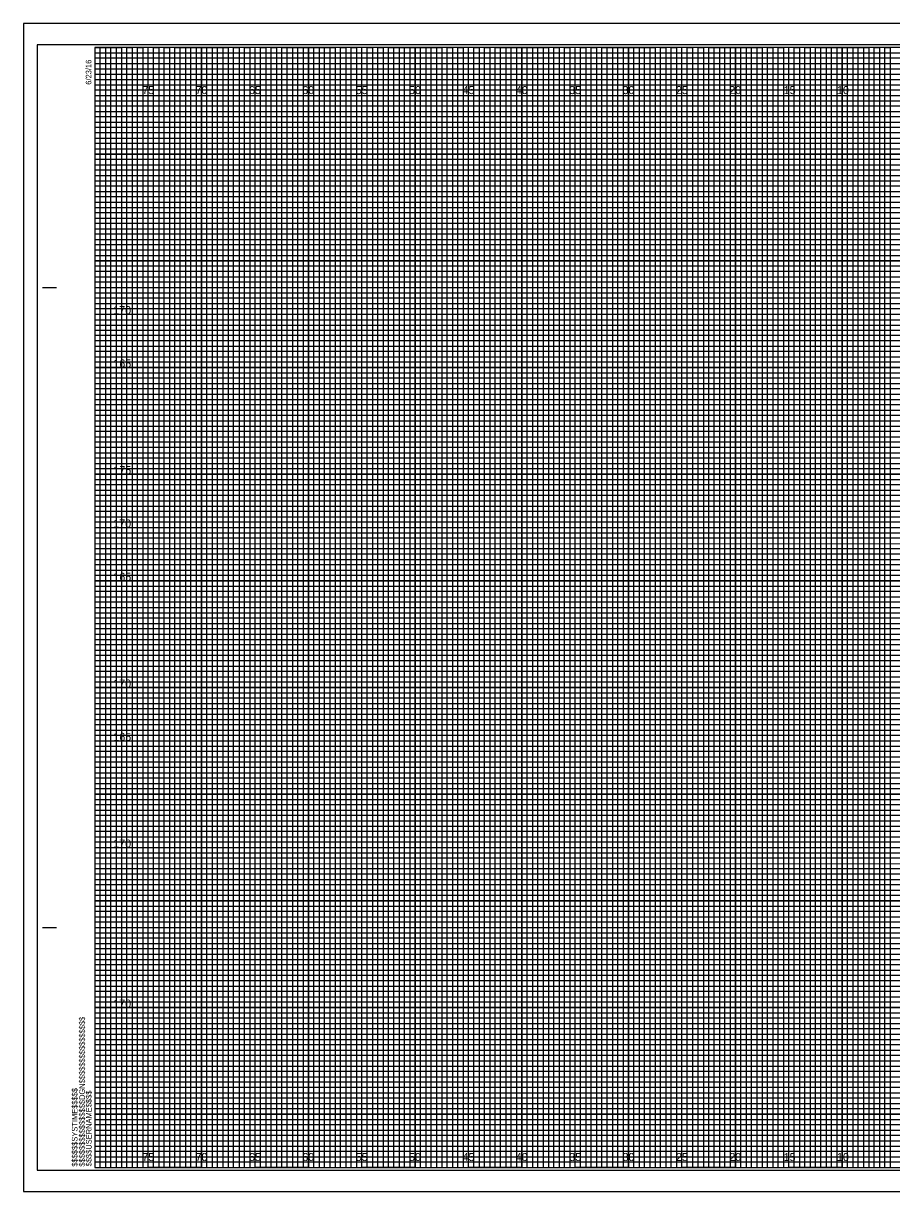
# Model space of a CAD drawing. Extents: x -7 to 162, y -2 to 107.
# Drawn here: x -6.7 to 74.6, y -2.3 to 107.3 of the extents above; entities that cross this region are included whole.
import ezdxf

# ---------------------------------------------------------------- set-up
doc = ezdxf.new("R2010")
doc.units = 0
for name, color, linetype in [('Prop XS Earthwork Shape', 7, 'Continuous'), ('Prop XS Elevation Labels', 7, 'Continuous'), ('Sheet Cross Section CELL', 7, 'Continuous'), ('Sheet Cross Section Grid Major CELL', 7, 'Continuous'), ('Sheet Cross Section Grid Middle CELL', 7, 'Continuous'), ('Sheet Cross Section Grid Minor 1 CELL', 7, 'Continuous'), ('Sheet Cross Section Grid Minor 2 CELL', 7, 'Continuous'), ('Sheet Cutting Line CELL', 7, 'Continuous'), ('Sheet DOT Grid CELL', 7, 'Continuous'), ('Sheet Plot Border Inside CELL', 7, 'Continuous'), ('Sheet Plot Border Outside CELL', 7, 'Continuous')]:
    doc.layers.add(name, color=color, linetype=linetype)

msp = doc.modelspace()

# ---------------------------------------------------------------- linework, layer by layer
at = {"layer": 'Sheet Cross Section CELL'}
for p, q in [((-4.9, 82.5), (-3.65, 82.5)), ((-4.85, 82.5), (-3.6, 82.5)), ((-4.9, 22.5), (-3.65, 22.5)), ((-4.85, 22.5), (-3.6, 22.5)), ((0, 0), (0, 0)), ((0, 0), (0, 0)), ((0, 0), (0, 0)), ((0, 0), (0, 0)), ((0, 0), (0, 0)), ((0, 0), (0, 0)), ((0, 0), (0, 0))]:
    msp.add_line(p, q, dxfattribs=at)
msp.add_lwpolyline([(160, 105), (0, 105), (0, 0), (160, 0)], close=True, dxfattribs=at)
at = {"layer": 'Sheet Cross Section Grid Major CELL'}
for p, q in [((5, 105), (0, 105)), ((5, 0), (5, 105)), ((15, 105), (10, 105)), ((10, 105), (10, 0)), ((15, 0), (15, 105)), ((25, 105), (20, 105)), ((20, 105), (20, 0)), ((25, 0), (25, 105)), ((35, 105), (30, 105)), ((30, 105), (30, 0)), ((35, 0), (35, 105)), ((45, 105), (40, 105)), ((40, 105), (40, 0)), ((45, 0), (45, 105)), ((55, 105), (50, 105)), ((50, 105), (50, 0)), ((55, 0), (55, 105)), ((65, 105), (60, 105)), ((60, 105), (60, 0)), ((65, 0), (65, 105)), ((75, 105), (70, 105)), ((70, 105), (70, 0)), ((10, 0), (5, 0)), ((20, 0), (15, 0)), ((30, 0), (25, 0)), ((40, 0), (35, 0)), ((50, 0), (45, 0)), ((60, 0), (55, 0)), ((70, 0), (65, 0))]:
    msp.add_line(p, q, dxfattribs=at)
for points in [[(0, 100), (160, 100), (160, 95), (0, 95)], [(0, 90), (160, 90), (160, 85), (0, 85)], [(0, 80), (160, 80), (160, 75), (0, 75)], [(0, 70), (160, 70), (160, 65), (0, 65)], [(0, 60), (160, 60), (160, 55), (0, 55)], [(0, 50), (160, 50), (160, 45), (0, 45)], [(0, 40), (160, 40), (160, 35), (0, 35)], [(0, 30), (160, 30), (160, 25), (0, 25)], [(0, 20), (160, 20), (160, 15), (0, 15)], [(0, 10), (160, 10), (160, 5), (0, 5)]]:
    msp.add_lwpolyline(points, dxfattribs=at)
at = {"layer": 'Sheet Cross Section Grid Middle CELL'}
for points in [[(0, 105), (2.5, 105), (2.5, 0), (7.5, 0), (7.5, 105), (12.5, 105), (12.5, 0), (17.5, 0), (17.5, 105), (22.5, 105), (22.5, 0), (27.5, 0), (27.5, 105), (32.5, 105), (32.5, 0), (37.5, 0), (37.5, 105), (42.5, 105), (42.5, 0), (47.5, 0), (47.5, 105), (52.5, 105), (52.5, 0), (57.5, 0), (57.5, 105), (62.5, 105), (62.5, 0), (67.5, 0), (67.5, 105), (72.5, 105), (72.5, 0), (77.5, 0)], [(0, 102.5), (137.5, 102.5)], [(0, 92.5), (160, 92.5), (160, 97.5), (0, 97.5)], [(0, 82.5), (160, 82.5), (160, 87.5), (0, 87.5)], [(0, 72.5), (160, 72.5), (160, 77.5), (0, 77.5)], [(0, 62.5), (160, 62.5), (160, 67.5), (0, 67.5)], [(0, 52.5), (160, 52.5), (160, 57.5), (0, 57.5)], [(0, 42.5), (160, 42.5), (160, 47.5), (0, 47.5)], [(0, 32.5), (160, 32.5), (160, 37.5), (0, 37.5)], [(0, 22.5), (160, 22.5), (160, 27.5), (0, 27.5)], [(0, 12.5), (160, 12.5), (160, 17.5), (0, 17.5)], [(0, 2.5), (160, 2.5), (160, 7.5), (0, 7.5)]]:
    msp.add_lwpolyline(points, dxfattribs=at)
at = {"layer": 'Sheet Cross Section Grid Minor 1 CELL'}
for p, q in [((0, 104.5), (130, 104.5)), ((130, 103.99), (0, 103.99)), ((0, 103.99), (0, 103.5)), ((0, 103.5), (130, 103.5)), ((130, 102.95), (0, 102.95)), ((0, 102.95), (0, 102)), ((0, 102), (160, 102))]:
    msp.add_line(p, q, dxfattribs=at)
for points in [[(0, 101.5), (135, 101.5), (160, 101.5), (160, 101), (0, 101)], [(0, 100.5), (160, 100.5), (160, 99.5), (0, 99.5)], [(0, 99), (160, 99), (160, 98.5), (0, 98.49)], [(0, 98), (160, 98), (160, 97), (0, 97)], [(0, 96.5), (160, 96.5), (160, 96), (0, 96)], [(0, 95.5), (160, 95.5), (160, 94.5), (0, 94.5)], [(0, 94), (160, 94), (160, 93.5), (0, 93.5)], [(0, 93), (160, 93), (160, 92), (0, 92)], [(0, 91.5), (160, 91.5), (160, 91), (0, 91)], [(0, 90.5), (160, 90.5), (160, 89.5), (0, 89.5)], [(0, 89), (160, 89), (160, 88.5), (0, 88.5)], [(0, 88), (160, 88), (160, 86.98), (160, 86.5), (160, 86), (0, 86)], [(0, 87), (160, 87), (160, 86.5), (0, 86.5)], [(0, 85.5), (160, 85.5), (160, 84.5), (0, 84.52)], [(0, 84.52), (160, 84.5), (160, 84), (0, 84)], [(0, 83.5), (160, 83.5), (160, 83), (0, 83)], [(0, 82), (160, 82), (160, 81.5), (0, 81.5)], [(0, 81), (160, 81), (160, 80.5), (0, 80.5)], [(-0.04, 79.45), (160, 79.45), (160, 78.94), (-0.04, 78.94)], [(0, 78.5), (160, 78.5), (160, 78), (0, 78)], [(0, 77), (160, 77), (160, 76.5), (0, 76.5)], [(0, 76), (160, 76), (160, 75.5), (0, 75.5)], [(0, 74.5), (160, 74.5), (160, 74), (0, 74)], [(0, 73.5), (160, 73.5), (160, 73), (0, 73)], [(0, 72), (160, 72), (160, 71.5), (0, 71.5)], [(0, 71), (160, 71), (160, 70.5), (0, 70.5)], [(0, 69.5), (160, 69.5), (160, 68.99), (0, 69)], [(0, 68.5), (160, 68.5), (160, 68), (0, 68)], [(0, 67), (160, 67), (160, 66.5), (0, 66.5)], [(0, 66), (160, 66), (160, 65.5), (0, 65.5)], [(0, 64.5), (160, 64.5), (160, 64), (0, 64)], [(0, 63.5), (160, 63.5), (160, 63), (0, 63)], [(0, 62), (160, 62), (160, 61.5), (0, 61.5)], [(0, 61), (160, 61), (160, 60.5), (0, 60.5)], [(0, 59.5), (160, 59.5), (160, 59), (0, 59)], [(0, 58.5), (160.03, 58.45), (160, 58), (0, 58)], [(0, 57), (160, 57), (160, 56.5), (0, 56.5)], [(0, 56), (160, 56), (160, 55.5), (0, 55.5)], [(0, 54.5), (160, 54.5), (160, 54), (0, 54)], [(0, 53.5), (160, 53.5), (160, 53), (0, 53)], [(0, 52), (160, 52), (160, 51.5), (0, 51.5)], [(0, 51), (160, 51), (160, 50.5), (0, 50.5)], [(0, 49.5), (160, 49.5), (160, 49), (0, 49)], [(0, 48.5), (160, 48.5), (160, 48), (0, 48)], [(0, 47), (160, 47), (160, 46.5), (0, 46.5)], [(0, 46), (160, 46), (160, 45.5), (0, 45.5)], [(0, 44.5), (160, 44.5), (160, 44), (0, 44)], [(0, 43.5), (160, 43.5), (160, 43), (0, 43)], [(0, 42), (160, 42), (160, 41.5), (0, 41.5)], [(0, 41), (160, 41), (160, 40.5), (0, 40.5)], [(0, 39.5), (160, 39.5), (160, 38.99), (0, 39)], [(0, 38.5), (160, 38.5), (160, 38), (0, 38)], [(0, 37), (160, 37), (160, 36.5), (0, 36.5)], [(0, 36), (160, 36), (160, 35.5), (0, 35.5)], [(0, 34.5), (160, 34.5), (160, 34), (0, 34)], [(0, 33.5), (160, 33.5), (160, 33), (0, 33)], [(0, 32), (160, 32), (160, 31.5), (0, 31.5)], [(0, 31), (160, 31), (160, 30.5), (0, 30.5)], [(0, 29.5), (160, 29.5), (160, 29), (0, 29)], [(0, 28.5), (160.03, 28.46), (160, 28), (0, 28)], [(0, 27), (160, 27), (160, 26.5), (0, 26.5)], [(0, 26), (160, 26), (160, 25.5), (0, 25.5)], [(0, 24.5), (160, 24.5), (160, 24), (0, 24)], [(0, 23.5), (160, 23.5), (160, 23), (0, 23)], [(0, 22), (160, 22), (160, 21.5), (0, 21.5)], [(0, 21), (160, 21), (160, 20.5), (0, 20.5)], [(0, 19.5), (160, 19.5), (160, 19), (0, 19)], [(0, 18.5), (160, 18.5), (160, 18), (0, 18)], [(0, 17), (160, 17), (160, 16.5), (0, 16.5)], [(0, 16), (160, 16), (160, 15.5), (0, 15.5)], [(0, 14.5), (160, 14.5), (160, 14), (0, 14)], [(0, 13.5), (160, 13.5), (160, 13), (0, 13)], [(0, 12), (160, 12), (160, 11.5), (0, 11.5)], [(0, 11), (160, 11), (160, 10.5), (0, 10.5)], [(0, 9.5), (160, 9.5), (160, 9), (0, 9)], [(0, 8.5), (160, 8.5), (160, 8), (0, 8)], [(0, 7), (160, 7), (160, 6.5), (0, 6.5)], [(0, 6), (160, 6), (160, 5.5), (0, 5.5)], [(0, 4.5), (160, 4.5), (160, 4), (0, 4)], [(0, 3.5), (160, 3.5), (160, 3), (0, 3)], [(0, 2), (160, 2), (160, 1.5), (0, 1.5)], [(0, 1), (160, 1), (160, 0.5), (0, 0.5)]]:
    msp.add_lwpolyline(points, dxfattribs=at)
at = {"layer": 'Sheet Cross Section Grid Minor 2 CELL'}
for points in [[(0, 0), (0.5, 0), (0.5, 105), (1, 105), (1, 0)], [(1, 0), (1.5, 0), (1.5, 105), (2, 105), (2, 0)], [(2.5, 0), (3, 0), (3, 105), (3.5, 105), (3.5, 0)], [(3.5, 0), (4, 0), (4, 105), (4.5, 105), (4.5, 0)], [(5, 0), (5.5, 0), (5.5, 105), (6, 105), (6, 0)], [(6, 0), (6.5, 0), (6.5, 105), (7, 105), (7, 0)], [(7.5, 0), (8, 0), (8, 105), (8.5, 105), (8.5, 0)], [(8.5, 0), (9, 0), (9, 105), (9.5, 105), (9.5, 0)], [(10, 0), (10.5, 0), (10.5, 105), (11, 105), (11, 0)], [(11, 0), (11.5, 0), (11.5, 105), (12, 105), (12, 0)], [(12.5, 0), (13, 0), (13, 105), (13.5, 105), (13.5, 0)], [(13.5, 0), (14, 0), (14, 105), (14.5, 105), (14.5, 0)], [(15, 0), (15.5, 0), (15.5, 105), (16, 105), (16, 0)], [(16, 0), (16.5, 0), (16.5, 105), (17, 105), (17, 0)], [(17.5, 0), (18, 0), (18, 105), (18.5, 105), (18.5, 0)], [(18.5, 0), (19, 0), (19, 105), (19.5, 105), (19.5, 0)], [(20, 0), (20.5, 0), (20.5, 105), (21, 105), (21, 0)], [(21, 0), (21.5, 0), (21.5, 105), (22, 105), (22, 0)], [(22.5, 0), (23, 0), (23, 105), (23.5, 105), (23.5, 0)], [(23.5, 0), (24, 0), (24, 105), (24.5, 105), (24.5, 0)], [(25, 0), (25.5, 0), (25.5, 105), (26, 105), (26, 0)], [(26, 0), (26.5, 0), (26.5, 105), (27, 105), (27, 0)], [(27.5, 0), (28, 0), (28, 105), (28.5, 105), (28.5, 0)], [(28.5, 0), (29, 0), (29, 105), (29.5, 105), (29.5, 0)], [(30, 0), (30.5, 0), (30.5, 105), (31, 105), (31, 0)], [(31, 0), (31.5, 0), (31.5, 105), (32, 105), (32, 0)], [(32.5, 0), (33, 0), (33, 105), (33.5, 105), (33.5, 0)], [(33.5, 0), (34, 0), (34, 105), (34.5, 105), (34.5, 0)], [(35, 0), (35.5, 0), (35.5, 105), (36, 105), (36, 0)], [(36, 0), (36.5, 0), (36.5, 105), (37, 105), (37, 0)], [(37.5, 0), (38, 0), (38, 105), (38.5, 105), (38.5, 0)], [(38.5, 0), (39, 0), (39, 105), (39.5, 105), (39.5, 0)], [(40, 0), (40.5, 0), (40.5, 105), (41, 105), (41, 0)], [(41, 0), (41.5, 0), (41.5, 105), (42, 105), (42, 0)], [(42.5, 0), (43, 0), (43, 105), (43.5, 105), (43.5, 0)], [(43.5, 0), (44, 0), (44, 105), (44.5, 105), (44.5, 0)], [(45, 0), (45.5, 0), (45.5, 105), (46, 105), (46, 0)], [(46, 0), (46.5, 0), (46.5, 105), (47, 105), (47, 0)], [(47.5, 0), (48, 0), (48, 105), (48.5, 105), (48.5, 0)], [(48.5, 0), (49, 0), (49, 105), (49.5, 105), (49.5, 0)], [(50, 0), (50.5, 0), (50.5, 105), (51, 105), (51, 0)], [(51, 0), (51.5, 0), (51.5, 105), (52, 105), (52, 0)], [(52.5, 0), (53, 0), (53, 105), (53.5, 105), (53.5, 0)], [(53.5, 0), (54, 0), (54, 105), (54.5, 105), (54.5, 0)], [(55, 0), (55.5, 0), (55.5, 105), (56, 105), (56, 0)], [(56, 0), (56.5, 0), (56.5, 105), (57, 105), (57, 0)], [(57.5, 0), (58, 0), (58, 105), (58.5, 105), (58.5, 0)], [(58.5, 0), (59, 0), (59, 105), (59.5, 105), (59.5, 0)], [(60, 0), (60.5, 0), (60.5, 105), (61, 105), (61, 0)], [(61, 0), (61.5, 0), (61.5, 105), (62, 105), (62, 0)], [(62.5, 0), (63, 0), (63, 105), (63.5, 105), (63.5, 0)], [(63.5, 0), (64, 0), (64, 105), (64.5, 105), (64.5, 0)], [(65, 0), (65.5, 0), (65.5, 105), (66, 105), (66, 0)], [(66, 0), (66.5, 0), (66.5, 105), (67, 105), (67, 0)], [(67.5, 0), (68, 0), (68, 105), (68.5, 105), (68.5, 0)], [(68.5, 0), (69, 0), (69, 105), (69.5, 105), (69.5, 0)], [(70, 0), (70.5, 0), (70.5, 105), (71, 105), (71, 0)], [(71, 0), (71.5, 0), (71.5, 105), (72, 105), (72, 0)], [(72.5, 0), (73, 0), (73, 105), (73.5, 105), (73.5, 0)], [(73.5, 0), (74, 0), (74, 105), (74.5, 105), (74.5, 0)]]:
    msp.add_lwpolyline(points, dxfattribs=at)
at = {"layer": 'Sheet Cutting Line CELL'}
for p, q in [((161.65, 107.25), (-6.7, 107.25)), ((-6.7, 107.25), (-6.7, -2.25)), ((-6.7, -2.25), (161.65, -2.25))]:
    msp.add_line(p, q, dxfattribs=at)
at = {"layer": 'Sheet DOT Grid CELL'}
for p, q in [((5, 0), (5, 105)), ((10, 0), (10, 105)), ((15, 0), (15, 105)), ((20, 0), (20, 105)), ((25, 0), (25, 105)), ((30, 0), (30, 105)), ((35, 0), (35, 105)), ((40, 0), (40, 105)), ((45, 0), (45, 105)), ((50, 0), (50, 105)), ((55, 0), (55, 105)), ((60, 0), (60, 105)), ((65, 0), (65, 105)), ((70, 0), (70, 105)), ((0, 100), (160, 100)), ((0, 95), (160, 95)), ((0, 90), (160, 90)), ((0, 85), (160, 85)), ((0, 80), (160, 80)), ((0, 75), (160, 75)), ((0, 70), (160, 70)), ((0, 65), (160, 65)), ((0, 60), (160, 60)), ((0, 55), (160, 55)), ((0, 50), (160, 50)), ((0, 45), (160, 45)), ((0, 40), (160, 40)), ((0, 35), (160, 35)), ((0, 30), (160, 30)), ((0, 25), (160, 25)), ((0, 20), (160, 20)), ((0, 15), (160, 15)), ((0, 10), (160, 10)), ((0, 5), (160, 5))]:
    msp.add_line(p, q, dxfattribs=at)
at = {"layer": 'Sheet Plot Border Inside CELL'}
msp.add_lwpolyline([(-5.4, -0.25), (161.2, -0.25), (161.2, 105.25), (-5.4, 105.25)], close=True, dxfattribs=at)
at = {"layer": 'Sheet Plot Border Outside CELL'}
msp.add_lwpolyline([(-6.7, -2.25), (161.65, -2.25), (161.65, 107.25), (-6.7, 107.25)], close=True, dxfattribs=at)

# ---------------------------------------------------------------- texts
at = {"layer": 'Prop XS Earthwork Shape'}
for s, p in [('75', (4.44, 100.62)), ('70', (9.43, 100.62)), ('65', (14.44, 100.62)), ('60', (19.43, 100.62)), ('55', (24.44, 100.62)), ('50', (29.43, 100.62)), ('45', (34.44, 100.62)), ('40', (39.43, 100.62)), ('35', (44.44, 100.62)), ('30', (49.43, 100.62)), ('25', (54.44, 100.62)), ('20', (59.43, 100.62)), ('15', (64.53, 100.62)), ('10', (69.52, 100.62)), ('75', (4.44, 0.62)), ('70', (9.43, 0.62)), ('65', (14.44, 0.62)), ('60', (19.43, 0.62)), ('55', (24.44, 0.62)), ('50', (29.43, 0.62)), ('45', (34.44, 0.62)), ('40', (39.43, 0.62)), ('35', (44.44, 0.62)), ('30', (49.43, 0.62)), ('25', (54.44, 0.62)), ('20', (59.43, 0.62)), ('15', (64.53, 0.62)), ('10', (69.52, 0.62))]:
    msp.add_text(s, height=0.75, dxfattribs=at).set_placement(p)
at = {"layer": 'Prop XS Elevation Labels'}
for s, p in [('170', (1.72, 80)), ('165', (1.73, 75)), ('175', (1.73, 65)), ('170', (1.72, 60)), ('165', (1.73, 55)), ('170', (1.72, 45)), ('165', (1.73, 40)), ('170', (1.72, 30)), ('170', (1.72, 15))]:
    msp.add_text(s, height=0.75, dxfattribs=at).set_placement(p)
at = {"layer": 'Sheet Cross Section CELL'}
for s, p in [('6/23/16', (-0.33, 101.5)), ('$$$$$$$$$$$$$$$$DGN$$$$$$$$$$$$$$$$', (-0.94, 0.09)), ('$$$$$$SYSTIME$$$$$', (-1.63, 0.09)), ('$$$$USERNAME$$$$', (-0.31, 0.12))]:
    msp.add_text(s, height=0.525, rotation=90, dxfattribs=at).set_placement(p)

doc.saveas('drawing.dxf')
